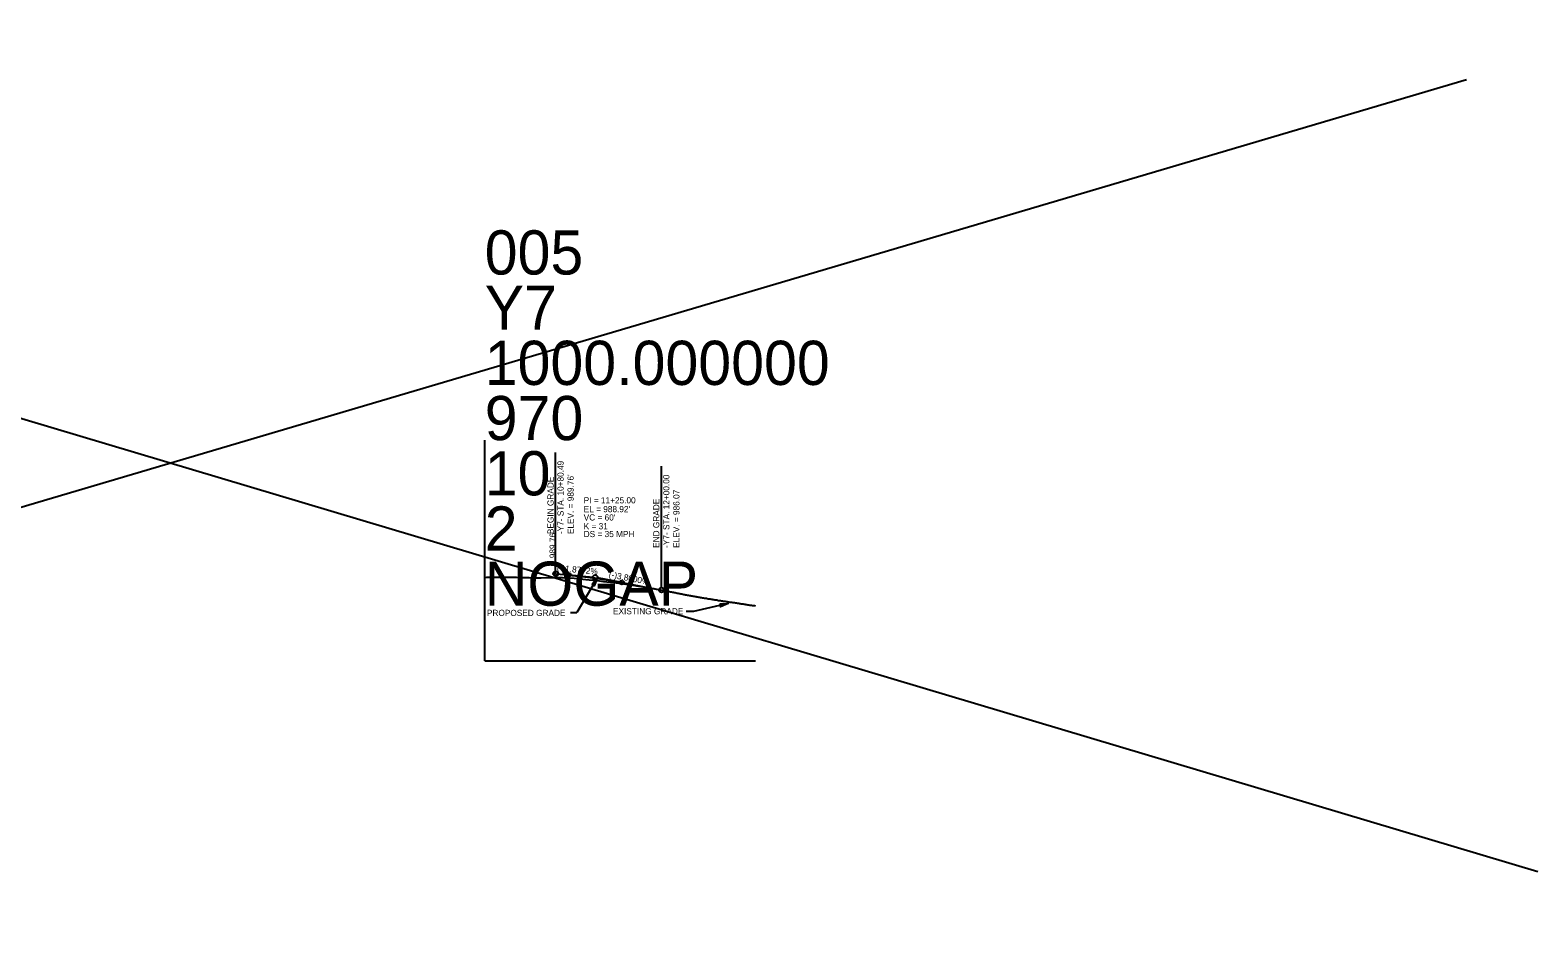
# Model space of a CAD drawing. Extents: x 1615624 to 1632571, y 894455 to 913418.
# Drawn here: x 1627212 to 1628918, y 899127 to 900148 of the extents above; entities that cross this region are included whole.
import ezdxf

# ---------------------------------------------------------------- set-up
doc = ezdxf.new("R2010")
doc.units = 0
for name, color, linetype in [('Exist Profile Cell', 7, 'Continuous'), ('Exist Vertical Profile Ground Line', 7, 'Continuous'), ('Prop Terminator CELL', 7, 'Continuous'), ('Prop Vertical Profile Curve Label', 7, 'Continuous'), ('Prop Vertical Profile Grade', 7, 'Continuous'), ('Prop Vertical Profile Grade Label', 7, 'Continuous'), ('Prop VPI Label', 7, 'Continuous')]:
    doc.layers.add(name, color=color, linetype=linetype)

msp = doc.modelspace()

# ---------------------------------------------------------------- linework, layer by layer
at = {"layer": 'Exist Profile Cell'}
for q in [(1627726.6, 899683.9), (1628032.9, 899433.9), (1627726.6, 899433.9)]:
    msp.add_line((1627726.6, 899433.9), q, dxfattribs=at)
at = {"layer": 'Exist Vertical Profile Ground Line'}
msp.add_lwpolyline([(1627726.6, 899528.2), (1627729.2, 899528.7), (1627731.8, 899528.8), (1627734.7, 899528.8), (1627741, 899528.8), (1627753.6, 899528.9), (1627755.7, 899528.7), (1627757.4, 899528.7), (1627759.4, 899528.8), (1627761, 899528.7), (1627762.6, 899528.8), (1627766.3, 899528.5), (1627767, 899528.5), (1627769, 899528.4), (1627771.2, 899528.3), (1627771.6, 899528.3), (1627776.2, 899528.2), (1627776.7, 899528.2), (1627777.1, 899528.2), (1627781.3, 899528), (1627782, 899527.9), (1627790.6, 899528.1), (1627798.4, 899528.2), (1627813.8, 899528.4), (1627814.6, 899528.4), (1627827.8, 899527.7), (1627834.4, 899527), (1627841, 899526.2), (1627856.5, 899524.5), (1627861, 899524), (1627872.6, 899522.6), (1627881.1, 899521.5), (1627894.1, 899519.6), (1627900.8, 899518.6), (1627918.1, 899515.8), (1627919.6, 899515.5), (1627929.4, 899513.7), (1627929.9, 899513.6), (1627930.5, 899513.5), (1627931.5, 899513.3), (1627932.6, 899513.1), (1627933.7, 899512.9), (1627934.7, 899512.7), (1627935.8, 899512.4), (1627936.9, 899512.2), (1627937.9, 899512), (1627939, 899511.8), (1627940.1, 899511.6), (1627941.1, 899511.4), (1627942.2, 899511.2), (1627943.3, 899511), (1627944.3, 899510.7), (1627945.4, 899510.5), (1627946.5, 899510.3), (1627947.5, 899510.1), (1627948.6, 899509.9), (1627949.7, 899509.7), (1627950.7, 899509.5), (1627951.8, 899509.3), (1627952.9, 899509.1), (1627953.9, 899508.9), (1627955, 899508.7), (1627956.1, 899508.5), (1627957.1, 899508.3), (1627958.2, 899508.1), (1627959.3, 899507.9), (1627960.3, 899507.7), (1627961.5, 899507.5), (1627962.5, 899507.3), (1627963.5, 899507.1), (1627964.6, 899507), (1627965.7, 899506.8), (1627966.7, 899506.6), (1627967.8, 899506.4), (1627968.9, 899506.2), (1627969.9, 899506), (1627970.6, 899505.9), (1627971, 899505.9), (1627972.1, 899505.7), (1627973.2, 899505.5), (1627974.2, 899505.3), (1627975.3, 899505.1), (1627976.4, 899504.9), (1627977.4, 899504.8), (1627978.5, 899504.6), (1627979.6, 899504.4), (1627980.6, 899504.2), (1627981.7, 899504.1), (1627982.8, 899503.9), (1627983.8, 899503.7), (1627984.9, 899503.5), (1627986, 899503.3), (1627987, 899503.2), (1627987.6, 899503.1), (1627988.2, 899503), (1627989.2, 899502.9), (1627990.2, 899502.7), (1627991.3, 899502.5), (1627992.4, 899502.4), (1627993.4, 899502.2), (1627994.5, 899502), (1627995.6, 899501.9), (1627996.6, 899501.7), (1627997.9, 899501.5), (1627998.4, 899501.4), (1627998.8, 899501.4), (1627999.8, 899501.2), (1628000.9, 899501.1), (1628002, 899500.9), (1628003, 899500.8), (1628004.1, 899500.6), (1628005.2, 899500.5), (1628006.2, 899500.3), (1628007.3, 899500.2), (1628008.4, 899500), (1628009.4, 899499.9), (1628010.5, 899499.7), (1628011.6, 899499.6), (1628012.8, 899499.4), (1628014.1, 899499.2), (1628014.8, 899499.1), (1628015.8, 899498.9), (1628016.9, 899498.7), (1628018, 899498.6), (1628019, 899498.4), (1628020.1, 899498.2), (1628021.2, 899498), (1628021.9, 899497.9), (1628022.3, 899497.9), (1628023.3, 899497.7), (1628024.4, 899497.6), (1628025.4, 899497.4), (1628026.5, 899497.2), (1628027.6, 899497.1), (1628028.6, 899496.9), (1628029.8, 899496.7), (1628030.8, 899496.6), (1628031.8, 899496.5), (1628032.9, 899496.3)], dxfattribs=at)
at = {"layer": 'Prop Terminator CELL'}
for points in [[(1627847.9, 899520.5), (1627853.8, 899527.5), (1627850.6, 899518.9), (1627849.8, 899520.7)], [(1627992.8, 899498.4), (1628001.9, 899498.9), (1627993.5, 899495.3), (1627994.2, 899497.1)]]:
    msp.add_lwpolyline(points, close=True, dxfattribs=at)
at = {"layer": 'Prop Vertical Profile Curve Label'}
for centre in [(1627821.6, 899531.3), (1627881.6, 899522.8)]:
    msp.add_circle(centre, 2.25, dxfattribs=at)
at = {"layer": 'Prop Vertical Profile Grade'}
for p, q in [((1627807, 899532.7), (1627821.6, 899531.3)), ((1627881.6, 899522.8), (1627926.6, 899514.2))]:
    msp.add_line(p, q, dxfattribs=at)
msp.add_spline([(1627821.6, 899531.3), (1627822.8, 899531.2), (1627824, 899531.1), (1627825.2, 899531), (1627826.4, 899530.8), (1627827.6, 899530.7), (1627828.8, 899530.6), (1627830, 899530.5), (1627831.2, 899530.3), (1627832.4, 899530.2), (1627833.6, 899530.1), (1627834.8, 899529.9), (1627836, 899529.8), (1627837.2, 899529.6), (1627838.4, 899529.5), (1627839.6, 899529.4), (1627840.8, 899529.2), (1627842, 899529.1), (1627843.2, 899528.9), (1627844.4, 899528.7), (1627845.6, 899528.6), (1627846.8, 899528.4), (1627848, 899528.3), (1627849.2, 899528.1), (1627850.4, 899527.9), (1627851.6, 899527.8), (1627852.8, 899527.6), (1627854, 899527.4), (1627855.2, 899527.2), (1627856.4, 899527.1), (1627857.6, 899526.9), (1627858.8, 899526.7), (1627860, 899526.5), (1627861.2, 899526.3), (1627862.4, 899526.1), (1627863.6, 899526), (1627864.8, 899525.8), (1627866, 899525.6), (1627867.2, 899525.4), (1627868.4, 899525.2), (1627869.6, 899525), (1627870.8, 899524.7), (1627872, 899524.5), (1627873.2, 899524.3), (1627874.4, 899524.1), (1627875.6, 899523.9), (1627876.8, 899523.7), (1627878, 899523.5), (1627879.2, 899523.2), (1627880.4, 899523), (1627881.6, 899522.8)], degree=3, dxfattribs=at)
at = {"layer": 'Prop VPI Label'}
for p, q in [((1625732.8, 900148.1), (1628918.2, 899195.6)), ((1625577.3, 899127.1), (1628837.4, 900092.1)), ((1628837.4, 900092.1), (1628837.4, 900092.1)), ((1627806.9, 899531.6), (1627806.9, 899669.9)), ((1627926.6, 899517), (1627926.6, 899654.3)), ((1627821.6, 899531.3), (1627848.8, 899528.7)), ((1627821.6, 899531.2), (1627848.8, 899528.3)), ((1627853.8, 899527.5), (1627831, 899488.8)), ((1627881.6, 899522.8), (1627854.3, 899528)), ((1628001.9, 899498.9), (1627962.7, 899489.7)), ((1627823.6, 899488.8), (1627831, 899488.8)), ((1627962.7, 899489.7), (1627954.4, 899489.7))]:
    msp.add_line(p, q, dxfattribs=at)
for centre in [(1627807, 899532.7), (1627851.6, 899528.5), (1627926.6, 899514.2)]:
    msp.add_circle(centre, 2.75, dxfattribs=at)

# ---------------------------------------------------------------- texts
at = {"layer": 'Exist Profile Cell'}
for s, p in [('005', (1627726.6, 899871.4)), ('Y7', (1627726.6, 899808.9)), ('1000.000000', (1627726.6, 899746.4)), ('970', (1627726.6, 899683.9)), ('10', (1627726.6, 899621.4)), ('2', (1627726.6, 899558.9)), ('NOGAP', (1627726.6, 899496.4))]:
    msp.add_text(s, height=50, dxfattribs=at).set_placement(p)
at = {"layer": 'Prop Vertical Profile Grade Label'}
for s, rotation, p in [('(-)1.8772%', 354.6376, (1627808.1, 899535.9)), ('(-)3.8000%', 349.242, (1627866.6, 899528.7))]:
    msp.add_text(s, height=7, rotation=rotation, dxfattribs=at).set_placement(p)
at = {"layer": 'Prop VPI Label'}
for s, p in [('-Y7- STA. 10+80.49', (1627815.9, 899577.5)), ('BEGIN GRADE', (1627804.6, 899577.5)), ("ELEV. = 989.76'", (1627827.3, 899577.5)), ('-Y7- STA. 12+00.00', (1627935.6, 899561.9)), ('END GRADE', (1627924.2, 899561.9)), ('ELEV. = 986.07', (1627947, 899561.9)), ('989.76', (1627807, 899550.2)), ('989.76', (1627807, 899550.2))]:
    msp.add_text(s, height=7, rotation=90, dxfattribs=at).set_placement(p)
for s, p in [('PI = 11+25.00', (1627838.6, 899612.3)), ("VC = 60'", (1627838.6, 899592.9)), ("EL = 988.92'", (1627838.6, 899602.3)), ('K = 31', (1627838.6, 899583)), ('DS = 35 MPH', (1627838.6, 899574.1)), ('PROPOSED GRADE', (1627729.1, 899484.8)), ('EXISTING GRADE', (1627871.8, 899486.7))]:
    msp.add_text(s, height=7, dxfattribs=at).set_placement(p)

doc.saveas('drawing.dxf')
